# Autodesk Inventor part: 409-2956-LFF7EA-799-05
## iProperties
Created: 2010-11
Part Number: 409-2956-LFF7EA-799-05
Material: 3/4" OD TUBE - SS
Document SubType Name: Modeling
Designer: S. Boerckel
Engineer: Steve Boerckel
Mass: 727.021 g
Surface Area: 1091.79 cm^2
Volume: 89.9779 cm^3
Density: 8.08 g/cm^3
Description: DRAIN TUBING
User Status: CUT/TUBE BEND
LGTH: 39.254 in
Author: S. Boerckel
Revision Number: 0
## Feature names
1. TaggingFeature1
